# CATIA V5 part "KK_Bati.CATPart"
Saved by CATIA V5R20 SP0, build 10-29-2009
Part number: Bati
Bounding box of the stored display mesh (mm): x -125.208 to 125.208, y -114.813 to 103.397, z -10 to 4.514
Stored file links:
  G:\Khaled_CFAO_2011\ST2M\ST2M_GR1\msallin\Khaled\Version_Finale\KK_Bati.CATPart
  C:\Users\Mathieu\Desktop\Think Motion\JOUG-MELEE2.CATProduct
  G:\Khaled_CFAO_2011\ST2M\ST2M_GR1\msallin\Assemblage Joug-Melee\Bati-Skl.CATPart
  G:\Khaled_CFAO_2011\ST2M\ST2M_GR1\msallin\Assemblage Joug-Melee\Verin2.CATPart
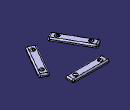
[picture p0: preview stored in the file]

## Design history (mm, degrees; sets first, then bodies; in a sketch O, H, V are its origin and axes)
Parameters
  LENGTH = 5 mm
External parameters (linked from other documents)
  `External.Taille du joug` = 100 mm
Set1
  Line1: linked copy from another document
  Point1: linked copy from another document
  Plane1: linked copy from another document
  Line2: linked copy from another document
Set2
  Plane2: type Offset, RefPlane xy-plane, Offset 10 {= `External.Taille du joug` /10}, reversed
Set3 "Pour les liaisons Cardan"
  Extract1: ExtractElem edge of DatumCurve1
  DatumCurve1
  Extract2: ExtractElem edge of DatumCurve2
  DatumCurve2
  Extract3: ExtractElem edge of DatumCurve3
  DatumCurve3
  Extract4: ExtractElem edge of DatumCurve4
  DatumCurve4
  Extract5: ExtractElem edge of DatumCurve5
  DatumCurve5
  Extract6: ExtractElem edge of DatumCurve6
  DatumCurve6
Body1 (main body)
  Sketch1 on Plane2, origin (0, 0, -10), H (1, 0, 0), V (0, 1, 0)
    point P1 (37.5, 86.7305)
    line L1 (75, 70.0638) -> (75, 103.3971)
    line L2 (75, 103.3971) -> (0, 103.3971)
    line L3 (0, 103.3971) -> (0, 70.0638)
    line L4 (0, 70.0638) -> (75, 70.0638)
    reference projected line E1 (-50.294, 86.4321) -> (49.7054, 86.7719) from Line1
    distance E1 P1 = 0
    distance V L3 = 0
    length L2 = 75 {= `External.Taille du joug` *3/2/2}
    length L1 = 33.3333 {= `External.Taille du joug` /3}
    vertical: L1 V, L3 V
    horizontal: L2 H, L4 H
    equidistance: L1 L3 P1, L2 L4 P1
  Sketch2 on Plane1, origin (-0.277, 81.5078, 20.3771), H (1, 0.0034, 0), V (0.0008, -0.2425, 0.9701)
    arc A1 centre (50, -21.0042) radius 5.1 from (45.2788, -19.0753) to (51.416, -25.9037) ccw
    reference projected point E1 (50, -21.0042) from Point1
    point P2 (45.2788, -19.0753)
    point P3 (51.416, -25.9037)
    reference projected line E2 (20.2094, 82.0734) -> (50, -21.0042) from Line2
    point P4 (45.2788, -19.0753)
    reference projected line E3 (20.2094, 82.0734) -> (50, -21.0042) from Line2
    point P5 (51.4993, -26.1919)
    reference projected line E4 (20.2094, 82.0734) -> (50, -21.0042) from Line2
    line L1 (51.416, -25.9037) -> (51.9713, -27.8251)
    line L2 (51.9713, -27.8251) -> (41.9713, -27.8251)
    line L3 (41.9713, -27.8251) -> (41.9713, -21.1584)
    line L4 (41.9713, -21.1584) -> (45.2788, -19.0753)
    radius A1 = 5.1 {= `External.Taille du joug` /20+`External.Taille du joug` /1000}
    distance E2 P3 = 0
    distance P2 E3 = 4 {= `External.Taille du joug` /25}
    distance P5 E4 = 0
    length L1 = 2 {= `External.Taille du joug` /50}
    length L2 = 10 {= `External.Taille du joug` /10}
    length L3 = 6.6667 {= `External.Taille du joug` /15}
    concentricity: E1 A1
    coincidence: P4 A1, P2 P4, L1 E1
    horizontal: L2 H
    vertical: L3 V
  Shaft1: profile Sketch2, axis Line2, angle 360
  Pad1: profile Sketch1, direction (0, 0, 1), length 10 {= `External.Taille du joug` /10}
  Mirror1: of the body so far, about yz-plane
  Fillet1: radius 5, on edge [face of Pad1 | face of Pad1] (x2); edge [face of Pad1 from Sketch1.L1 | face of Pad1] (x2); edge [face of Pad1 | face of Mirror1] (x2); edge [face of Pad1 | face of Pad1 from Sketch1.L1]; edge [face of Mirror1 | face of Pad1]
  Fillet2: radius 5, on edge [face of Shaft1 from Sketch2.L4 | face of Shaft1 from Sketch2.L3]; edge [face of Mirror1 | face of Mirror1]
  CircPattern1: of the body so far, instances 3, angular step 120, axis from xy-plane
